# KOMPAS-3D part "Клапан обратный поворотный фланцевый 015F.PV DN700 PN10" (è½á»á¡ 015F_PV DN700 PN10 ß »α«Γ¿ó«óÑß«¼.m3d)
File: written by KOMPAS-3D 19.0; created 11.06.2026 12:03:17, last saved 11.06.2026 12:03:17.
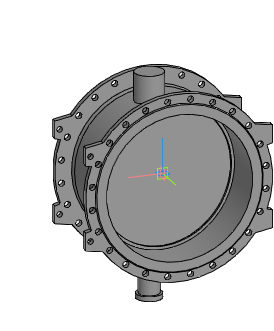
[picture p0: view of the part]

Document properties: Автор: Энергия; Полное имя файла: Z:\3.Личные\kachalov\001_3d для проектировщиков\5.5 Тип 015F.PV Клапан обратный поворотный с двумя эксцентриками\_stp_Клапан 015F.PV DN300-DN1200 с противовесом\Клапан 015F_PV DN700 PN10 с противовесом.m3d

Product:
- Part/product: Клапан обратный поворотный фланцевый 015F.PV DN700 PN10

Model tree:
1. Операция без истории:1
2. Сплайн:1
     Координата Y = 30; Координата Z = 350; Вес = 1; Координата X = 700; Координата Y = 122.157; Координата Z = 350; Вес = 0.333333; Координата X = 700; Координата Y = 122.157; Координата Z = -350; Вес = 0.333333; Координата Y = 30; Координата Z = -350; Вес = 1; Координата X = -700; Координата Y = -62.1567; Координата Z = -350; Вес = 0.333333; Координата X = -700; Координата Y = -62.1567; Координата Z = 350; Вес = 0.333333; Порядок = 4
